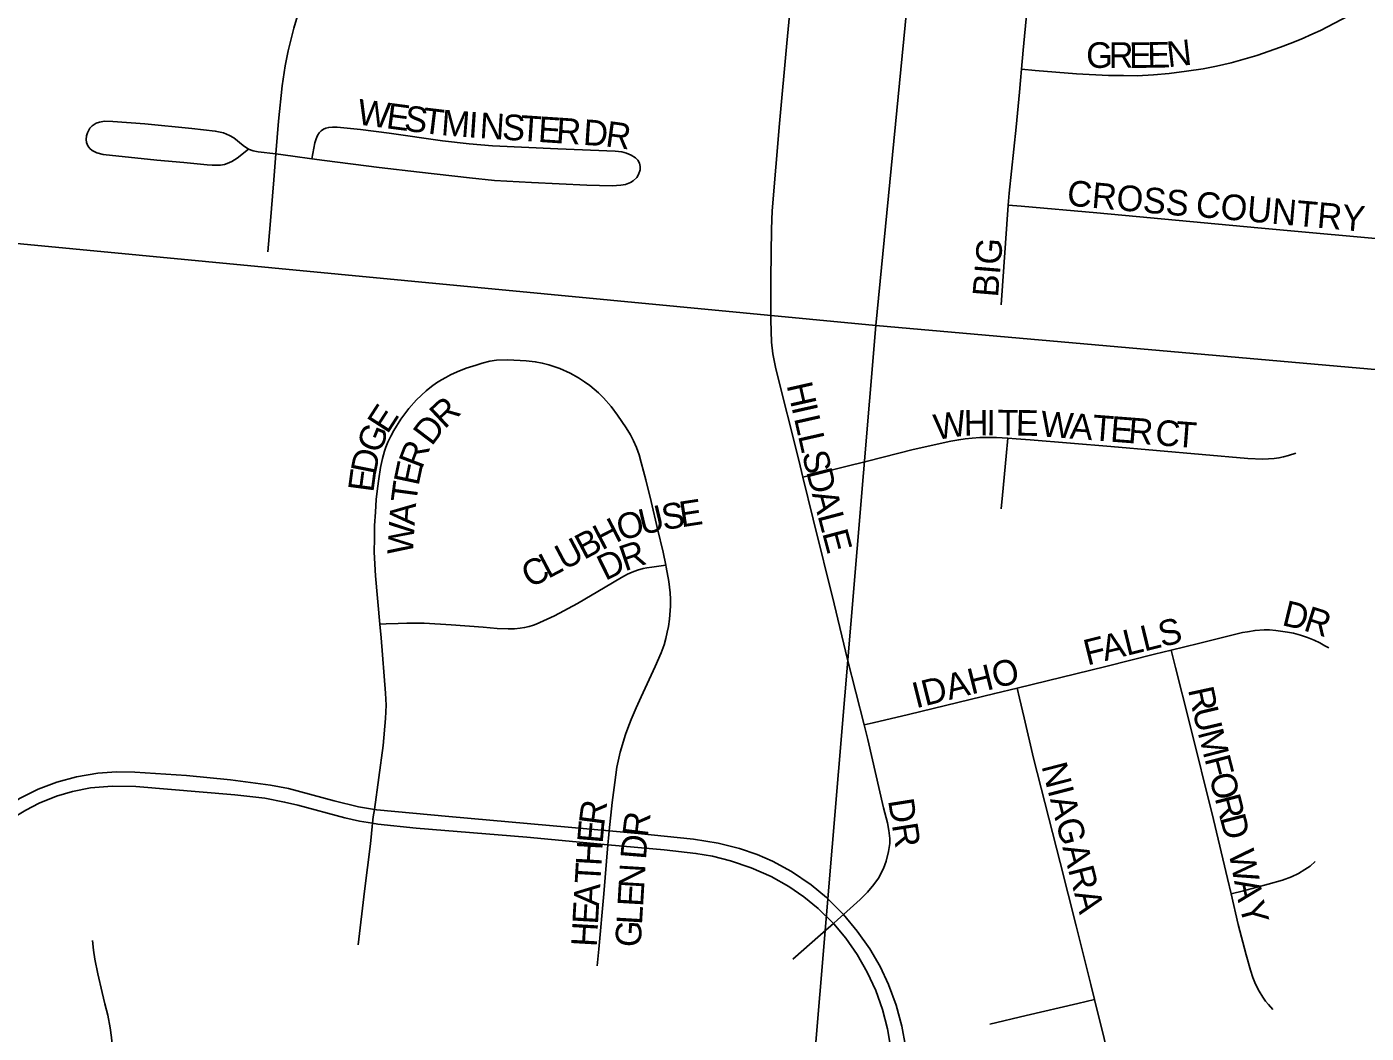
# Model space of a CAD drawing. Extents: x 1410790 to 1770854, y 448063 to 770588.
# Drawn here: x 1532952 to 1535566, y 644079 to 646042 of the extents above; entities that cross this region are included whole.
import ezdxf

# ---------------------------------------------------------------- set-up
doc = ezdxf.new("R2010")
doc.units = 0
for name, color, linetype in [('GM_X_City_Street', 7, 'Continuous'), ('GM_X_City_Street_Text', 7, 'Continuous'), ('GM_X_Section', 7, 'Continuous')]:
    doc.layers.add(name, color=color, linetype=linetype)

msp = doc.modelspace()

# ---------------------------------------------------------------- linework, layer by layer
at = {"layer": 'GM_X_City_Street'}
for points in [[(1534893.3, 645959.4), (1534896.6, 645996.5), (1534903.8, 646071.6), (1534911, 646143.3), (1534916.5, 646202.1), (1534924.4, 646283.3), (1534930.7, 646351.9), (1534938.8, 646435.8)], [(1534466.8, 645163.3), (1534458.7, 645196.4), (1534413.8, 645374.7), (1534408.1, 645404), (1534405.2, 645427.1), (1534404.1, 645470), (1534404.1, 645552.1), (1534405.1, 645647.3), (1534406.6, 645683.5), (1534420.8, 645853.5), (1534435.5, 646010.2), (1534453.9, 646209.5), (1534462.6, 646304)], [(1533438.1, 645794.5), (1533443.1, 645858.3), (1533450.3, 645926.9), (1533456.4, 645966), (1533462, 645995.2), (1533473.2, 646039.9), (1533494.4, 646112.5), (1533502.8, 646139.7)], [(1534893.3, 645959.4), (1534919.8, 645956.9), (1535000.6, 645950.6), (1535063.2, 645947), (1535092.5, 645947.1), (1535118.7, 645946.9), (1535150.7, 645948.5), (1535181.5, 645951), (1535215.2, 645955.6), (1535247.8, 645960.6), (1535273.7, 645965.7), (1535302.1, 645972.2), (1535352.5, 645986.4), (1535398.4, 646002.4), (1535417.7, 646009.9), (1535439.1, 646018.4), (1535461.7, 646028.5), (1535476.5, 646035.2), (1535531.6, 646063.4)], [(1534867.5, 645694.5), (1534869.2, 645717.4), (1534882.5, 645846.6), (1534889.2, 645914.9), (1534891.4, 645937.8), (1534893.3, 645959.4)], [(1533384.7, 645803.8), (1533362.4, 645786), (1533352.1, 645779.5), (1533343.1, 645775.3), (1533337.7, 645773.5), (1533330.3, 645772.4), (1533321.9, 645772.2), (1533314, 645772.3), (1533304.2, 645773), (1533258.5, 645777.6), (1533206.1, 645782), (1533101.4, 645793.1), (1533088.6, 645796.2), (1533079.9, 645800.8), (1533075, 645805.1), (1533071.2, 645810.3), (1533068.8, 645816.3), (1533067.8, 645822.7), (1533068.3, 645829.3), (1533070.2, 645835.7), (1533075.1, 645844.2), (1533079.6, 645848.9), (1533087.7, 645854.3), (1533093.8, 645856.5), (1533103.6, 645858), (1533120.1, 645857.6), (1533182.4, 645853.1), (1533273.9, 645843.9), (1533319.7, 645838.9), (1533335.7, 645835.5), (1533347.7, 645830.5), (1533356.1, 645825.5), (1533374, 645810.9), (1533384.7, 645803.8)], [(1533508.4, 645784.7), (1533532.7, 645781.3), (1533640, 645767.9), (1533718.3, 645758.8), (1533816, 645747.3), (1533865, 645742.7), (1533937, 645738.3), (1534045.1, 645733.3), (1534094.5, 645732), (1534111, 645733.1), (1534120.7, 645734.9), (1534130, 645738.5), (1534135.4, 645741.7), (1534142.6, 645748.5), (1534146.1, 645753.9), (1534149, 645763.1), (1534149.1, 645769.7), (1534147.6, 645776.1), (1534144.6, 645781.8), (1534139.9, 645786.5), (1534131.5, 645791.7), (1534122.6, 645795.8), (1534113.1, 645798.5), (1534100.1, 645799.8), (1533988.7, 645804.1), (1533860.9, 645810.2), (1533815.1, 645813.9), (1533763, 645820.1), (1533658.9, 645834.8), (1533603.5, 645841.6), (1533557.9, 645846.2), (1533548.7, 645846.5), (1533541.4, 645845.9), (1533535.7, 645844.4), (1533531.3, 645842.7), (1533526.8, 645839.5), (1533522.6, 645835.1), (1533519.4, 645830.2), (1533516.7, 645823.5), (1533514.4, 645816.1), (1533508.4, 645784.7)], [(1533384.7, 645803.8), (1533393.9, 645800.1), (1533403.7, 645798.5), (1533438.1, 645794.5)], [(1533422.3, 645603.3), (1533426.7, 645655.8), (1533434.1, 645743.7), (1533438.1, 645794.5)], [(1533438.1, 645794.5), (1533470.9, 645789.9), (1533508.4, 645784.7)], [(1534853.6, 645500.1), (1534867.5, 645694.5)], [(1534867.5, 645694.5), (1534892.4, 645692.3), (1535040.5, 645679.2), (1535354.4, 645650.3), (1535648.3, 645623.2), (1535720.3, 645616.5), (1535763, 645614.2), (1535783.2, 645613.6), (1535803.3, 645615.5), (1535820.8, 645618.8)], [(1533641, 644876.6), (1533632.5, 644971.3), (1533630.1, 645016.9), (1533630.4, 645044.4), (1533630.9, 645068.9), (1533632.4, 645095.4), (1533634.1, 645120.2), (1533636.5, 645141.4), (1533638.8, 645160.1), (1533642.4, 645182.6), (1533646, 645200), (1533650, 645214.1), (1533652.8, 645221.9), (1533656.8, 645231.6), (1533662.2, 645243.5), (1533668.6, 645254.7), (1533682.1, 645276.8), (1533697.3, 645297.8), (1533712.4, 645314.6), (1533731.3, 645332.1), (1533741.6, 645340.5), (1533751.8, 645347.8), (1533761.3, 645353.3), (1533769.6, 645358.1), (1533779, 645363.5), (1533791.9, 645368.9), (1533809.8, 645376.1), (1533828.7, 645382.1)], [(1534199.2, 644991.7), (1534193.8, 645017.4), (1534183.2, 645062.8), (1534170.6, 645115.9), (1534160.2, 645158), (1534151.2, 645192.4), (1534146.9, 645206.8), (1534141.8, 645221.2), (1534136.3, 645234.6), (1534130.4, 645246), (1534121.8, 645259.7), (1534104.8, 645284.8), (1534092.6, 645301.3), (1534077.5, 645318.2), (1534067.7, 645327.9), (1534050.6, 645342.4), (1534040.2, 645349.5), (1534029, 645357.4), (1534012.5, 645366.3), (1533992, 645375.4), (1533970.8, 645382.7), (1533957.9, 645386.1), (1533944.2, 645388.7), (1533926.7, 645390.8), (1533891.1, 645392.4), (1533868.6, 645391.7), (1533855.5, 645389.8), (1533840.7, 645386.1), (1533828.7, 645382.1)], [(1534466.8, 645163.3), (1534500.4, 645171.7), (1534592.5, 645194.6), (1534681.7, 645217.2), (1534755.5, 645233.8), (1534770.8, 645236.5), (1534783.6, 645238.4), (1534797, 645239.9), (1534811.6, 645240.8), (1534828.1, 645240.9), (1534844.6, 645240.8), (1534866.4, 645239.4)], [(1534853.8, 645102), (1534856.2, 645128.5), (1534863.2, 645204.5), (1534866.4, 645239.4)], [(1534866.4, 645239.4), (1534882.9, 645238.4), (1534910.3, 645236.6), (1535067.3, 645223.4), (1535335.1, 645199.9), (1535364.2, 645198.8), (1535375.3, 645199.1), (1535386.6, 645199.7), (1535395.7, 645201.2), (1535404.5, 645203), (1535414.6, 645205.8), (1535428.6, 645210.4)], [(1534586, 644680.1), (1534553.8, 644807.8), (1534527.6, 644916.2), (1534486.8, 645081.8), (1534466.8, 645163.3)], [(1533641, 644876.6), (1533653.2, 644877), (1533676.9, 644877.7), (1533693.4, 644878.4), (1533727.4, 644878.7), (1533780, 644875.5), (1533842.5, 644870.5), (1533869.8, 644868), (1533891.7, 644867.3), (1533903.6, 644867.6), (1533914.8, 644868.7), (1533923.4, 644870.1), (1533932.7, 644872.3), (1533940.7, 644874.9), (1533946.3, 644876.9), (1533982, 644892.8), (1534026.5, 644917.2), (1534080.8, 644948.8), (1534112.8, 644967.4), (1534124.3, 644974), (1534133.3, 644978.3), (1534144, 644982.3), (1534155, 644985.5), (1534162.1, 644986.5), (1534171.8, 644987.9), (1534199.2, 644991.7)], [(1534088.7, 644473.3), (1534094.7, 644529), (1534099.6, 644568), (1534103.8, 644597.5), (1534110, 644626.6), (1534120.5, 644661.5), (1534124.9, 644673.5), (1534131.8, 644690.8), (1534141.5, 644713.4), (1534151, 644734.6), (1534178.4, 644794.2), (1534190.3, 644820.9), (1534195.8, 644836.4), (1534199.4, 644848.6), (1534201.9, 644860.8), (1534204.4, 644872.3), (1534206.3, 644886.1), (1534208.3, 644911.8), (1534208.3, 644925.5), (1534207.7, 644937.5), (1534205, 644959.8), (1534200.1, 644987.7), (1534199.2, 644991.7)], [(1533630.3, 644515.1), (1533638.9, 644577.7), (1533647.2, 644639.7), (1533652.1, 644692.3), (1533653.1, 644718.9), (1533652.1, 644742.1), (1533643.3, 644850.3), (1533641, 644876.6)], [(1535185.1, 644825.9), (1535238.8, 644839), (1535324.7, 644860.1), (1535334.4, 644862), (1535349.1, 644864.5), (1535366.7, 644865.8), (1535377, 644865.5), (1535389.6, 644864.6), (1535412.3, 644861.2), (1535423.9, 644858.8), (1535437.7, 644855.1), (1535451.2, 644850.5), (1535464.5, 644845.2), (1535475.5, 644840.2), (1535485.5, 644834.7), (1535493.1, 644830.2)], [(1534884.8, 644752), (1535057.6, 644794), (1535152.9, 644818), (1535185.1, 644825.9)], [(1535302.3, 644350.3), (1535295.4, 644380.7), (1535267.8, 644495.7), (1535220.6, 644687), (1535193.7, 644792), (1535185.1, 644825.9)], [(1534586, 644680.1), (1534603.5, 644684.2), (1534672.5, 644700.3), (1534841.1, 644741.4), (1534884.8, 644752)], [(1535035.7, 644144.1), (1535028.5, 644173.3), (1534999.9, 644287.8), (1534968.9, 644411.8), (1534916.9, 644614.9), (1534898.2, 644694.2), (1534889.4, 644732.2), (1534884.8, 644752)], [(1534545.7, 644310), (1534578.3, 644339.4), (1534592.6, 644353.5), (1534604.9, 644368.5), (1534614, 644380.8), (1534623.8, 644399.6), (1534629.4, 644414.5), (1534634, 644433), (1534636, 644448.6), (1534636.5, 644458.5), (1534634.4, 644474), (1534631.7, 644489), (1534624.2, 644518.4), (1534593.1, 644651.8), (1534586, 644680.1)], [(1532753, 644406.7), (1532763.3, 644418.3), (1532779.9, 644432.8), (1532797.4, 644445), (1532821.9, 644460.7), (1532899.7, 644512.8), (1532938.8, 644536.9), (1532974.1, 644554.5), (1533010.8, 644568.5), (1533048.8, 644578.7), (1533090.9, 644585.8), (1533126.9, 644588.5), (1533163, 644588), (1533264, 644581.6), (1533349.7, 644572.6), (1533427.6, 644562.7), (1533462.9, 644555.7), (1533551.9, 644532.2), (1533599.6, 644520.2), (1533630.3, 644515.1)], [(1532753, 644406.7), (1532771.6, 644407.6), (1532786.3, 644410.4), (1532797.1, 644413.7), (1532811.5, 644419.6), (1532850.3, 644444.6), (1532922.2, 644496.5), (1532950.1, 644513.8), (1532976.3, 644527.4), (1533009.7, 644541), (1533041, 644550.4), (1533076.4, 644557.3), (1533118.9, 644560.8), (1533164.8, 644559.8), (1533357.8, 644543.6), (1533416.5, 644536.9), (1533455.1, 644529.6), (1533480.7, 644523.5), (1533572.5, 644498.7), (1533601.4, 644492.5), (1533627, 644488.3)], [(1533628.3, 644500.4), (1533630.3, 644515.1)], [(1533630.3, 644515.1), (1533635.1, 644514.3), (1533775.7, 644501.4), (1534088.7, 644473.3)], [(1533598.7, 644250.8), (1533610.8, 644355.7), (1533622.5, 644448.1), (1533627, 644488.3)], [(1533627, 644488.3), (1533628.3, 644500.4)], [(1533627, 644488.3), (1533637, 644486.7), (1533712, 644478.6), (1533927.9, 644461.3), (1534086.1, 644446.4)], [(1534086.1, 644446.4), (1534087.2, 644458.8)], [(1534087.2, 644458.8), (1534088.7, 644473.3)], [(1534088.7, 644473.3), (1534145.2, 644468.2), (1534252.9, 644456.9), (1534301.5, 644449.2), (1534343, 644439.2), (1534377.1, 644427.5), (1534407.2, 644414.4), (1534444.6, 644394), (1534482.7, 644368.2), (1534513, 644343.1), (1534543.2, 644313), (1534545.7, 644310)], [(1534065.1, 644209.8), (1534068.3, 644242.6), (1534078, 644350.7), (1534086.1, 644446.4)], [(1534086.1, 644446.4), (1534195.8, 644436.1), (1534257.8, 644429.3), (1534290.1, 644423.7), (1534325.1, 644415.1), (1534365.5, 644401.4), (1534404.5, 644384.1), (1534438.9, 644365), (1534468.7, 644344.7), (1534496.6, 644321.8), (1534526.1, 644292.5)], [(1535302.3, 644350.3), (1535326.5, 644356.6), (1535374.6, 644369.1), (1535402.8, 644377.4), (1535420.4, 644383.9), (1535433.8, 644389.9), (1535446.2, 644397.8), (1535456.4, 644404.2), (1535466.6, 644413.5)], [(1535383.4, 644125), (1535375.1, 644134.4), (1535369.5, 644141.1), (1535364.2, 644148.7), (1535357, 644160.6), (1535350.1, 644174), (1535345, 644186.9), (1535340.4, 644201.2), (1535331.6, 644231.3), (1535315.9, 644290.9), (1535302.3, 644350.3)], [(1534535, 644300.4), (1534545.7, 644310)], [(1534545.7, 644310), (1534572.7, 644277.7), (1534597.3, 644242.9), (1534617.1, 644208.9), (1534634, 644173.3), (1534648.7, 644133.3), (1534659.8, 644092.1), (1534666.7, 644053.3), (1534670, 644014.1), (1534669.5, 643971.4), (1534658.6, 643842.5), (1534650.1, 643749)], [(1534446.8, 644222.8), (1534501.1, 644270.5), (1534526.1, 644292.5)], [(1534526.1, 644292.5), (1534535, 644300.4)], [(1534526.1, 644292.5), (1534526.9, 644291.8), (1534550.1, 644264.2), (1534572.6, 644231.9), (1534592.2, 644197.8), (1534608.7, 644162), (1534622, 644125), (1534632, 644086.9), (1534639, 644044.8), (1534642.1, 644005.6), (1534641.1, 643959.6), (1534622.7, 643751.6)], [(1533087.6, 643601.4), (1533091.2, 643641.3), (1533100.3, 643745.9), (1533106.3, 643811.2), (1533112.6, 643893.6), (1533116.3, 643933.9), (1533118.5, 643968.4), (1533119.9, 643986), (1533120.8, 643999.6), (1533120.3, 644021.8), (1533119.4, 644049.9), (1533117.6, 644069.9), (1533114.7, 644088.9), (1533110.4, 644113.9), (1533104.5, 644135.6), (1533099, 644157.7), (1533090.4, 644194.3), (1533084.5, 644223.3), (1533082.3, 644240.6), (1533080, 644259.2)], [(1534831.5, 644096.2), (1534902.1, 644113), (1535003.2, 644136.5), (1535035.7, 644144.1)], [(1534980.8, 643755.3), (1534981.3, 643755.6), (1534996.6, 643766.2), (1535006.3, 643773.7), (1535018.2, 643784), (1535028.3, 643793.7), (1535035.5, 643801.8), (1535041.5, 643809.7), (1535047.6, 643817.7), (1535057.9, 643835.1), (1535066.2, 643853.4), (1535072.7, 643872.5), (1535077.8, 643895.5), (1535080.2, 643915.5), (1535080.8, 643926.1), (1535080.5, 643935.7), (1535078.7, 643955.7), (1535072.9, 643985.1), (1535054.5, 644068.3), (1535035.7, 644144.1)]]:
    msp.add_lwpolyline(points, dxfattribs=at)
at = {"layer": 'GM_X_Section'}
for points in [[(1535136.5, 650861.1), (1534609.1, 645459.7), (1529389.2, 645957.9), (1529818.7, 651249.1)], [(1540640, 650339.9), (1540107.2, 644974.6), (1534609.1, 645459.7), (1535136.5, 650861.1)], [(1534609.1, 645459.7), (1534160.3, 640098.2), (1528881.3, 640647.9), (1529389.2, 645957.9)], [(1534609.1, 645459.7), (1540107.2, 644974.6), (1539587.8, 639581.9), (1534160.3, 640098.2)]]:
    msp.add_lwpolyline(points, close=True, dxfattribs=at)

# ---------------------------------------------------------------- texts
at = {"layer": 'GM_X_City_Street_Text'}
for s, rotation, p in [('G', 0.0656, (1535019.5, 645962.1)), ('R', 0.0653, (1535063.5, 645962.2)), ('E', 0.0546, (1535103.1, 645962.2)), ('E', 0.9681, (1535139.1, 645962.3)), ('N', 6.4207, (1535179.5, 645963.2)), ('W', 352.5309, (1533595.1, 645852.1)), ('E', 352.5209, (1533651.8, 645844.6)), ('S', 352.5209, (1533686.7, 645840)), ('T', 353.0071, (1533722.1, 645835.4)), ('M', 355.6007, (1533759.5, 645830.9)), ('I', 356.2222, (1533812.7, 645826.8)), ('N', 356.2432, (1533834.7, 645825.3)), ('S', 356.2268, (1533878.6, 645822.4)), ('T', 356.2268, (1533913.7, 645820.1)), ('E', 356.2268, (1533948.8, 645817.8)), ('R', 356.2356, (1533984, 645815.5)), ('D', 356.2323, (1534036.7, 645812)), ('R', 352.2786, (1534079.7, 645809.2)), ('CROSS', 354.8033, (1534980.7, 645693.7)), ('COUNTRY', 354.8803, (1535231.9, 645671.7)), ('BIG', 85.2386, (1534847.3, 645513.5)), ('H', 282.6948, (1534434.6, 645343.2)), ('E', 57.1433, (1533655.8, 645246.1)), ('R', 43.1707, (1533767.3, 645256.1)), ('I', 282.6792, (1534444.3, 645300.3)), ('W', 8.8791, (1534726.2, 645235.8)), ('H', 0.6338, (1534780.8, 645244.4)), ('I', 359.9126, (1534824.6, 645244.9)), ('T', 359.939, (1534846.7, 645244.9)), ('E', 358.6338, (1534881.6, 645244.9)), ('D', 52.8372, (1533742.2, 645222.7)), ('L', 282.6995, (1534449.1, 645278.8)), ('W', 355.6922, (1534929.3, 645243.3)), ('A', 355.6021, (1534986.3, 645239)), ('T', 355.5971, (1535030.1, 645235.7)), ('E', 355.6001, (1535065.3, 645233)), ('R', 355.6004, (1535100.3, 645230.3)), ('C', 355.6165, (1535153, 645226.2)), ('T', 355.5971, (1535192.5, 645223.2)), ('G', 68.3082, (1533640.7, 645207.5)), ('L', 282.6977, (1534456.9, 645244.5)), ('D', 78.7586, (1533632.8, 645166.7)), ('R', 68.9607, (1533723.1, 645177.6)), ('E', 78.0846, (1533716.4, 645145.2)), ('S', 282.9013, (1534464.7, 645209.9)), ('E', 82.4243, (1533628.3, 645132.6)), ('D', 284.261, (1534472.8, 645174.4)), ('T', 82.3837, (1533711.9, 645111.2)), ('A', 85.8443, (1533708.8, 645068.2)), ('S', 8.7503, (1534194.6, 645060.1)), ('E', 8.7503, (1534229.4, 645065.5)), ('A', 284.8099, (1534483.8, 645131.2)), ('O', 14.5823, (1534110.5, 645039.3)), ('U', 13.2092, (1534152.8, 645050.3)), ('L', 284.8242, (1534495, 645088.6)), ('W', 86.7362, (1533705.5, 645011.3)), ('B', 27.8693, (1534039.3, 645001.6)), ('H', 27.3666, (1534074.2, 645020.1)), ('E', 284.8415, (1534504, 645054.6)), ('U', 27.8598, (1534000.4, 644981.1)), ('R', 18.8459, (1534119.1, 644979.4)), ('L', 27.8603, (1533969.3, 644964.6)), ('D', 26.2865, (1534081.2, 644960.6)), ('C', 27.8739, (1533934.2, 644946.1)), ('D', 346.2977, (1535399.6, 644875.2)), ('R', 342.5098, (1535441.5, 644865)), ('S', 13.7944, (1535166.9, 644831.6)), ('F', 13.8209, (1535021.6, 644795.9)), ('A', 13.7924, (1535055.8, 644804.3)), ('L', 13.8076, (1535098.6, 644814.8)), ('L', 13.8209, (1535132.7, 644823.2)), ('IDAHO', 14.0339, (1534687.2, 644712.3)), ('R', 282.1626, (1535217.9, 644749.1)), ('U', 283.2776, (1535226.5, 644709.4)), ('M', 284.5022, (1535236.9, 644665.4)), ('F', 284.5443, (1535250.1, 644614.2)), ('NIAGARA', 284.4709, (1534931.8, 644599.9)), ('O', 284.5345, (1535258.9, 644580.2)), ('R', 284.5349, (1535270, 644537.6)), ('R', 82.4503, (1534078.7, 644482.3)), ('DR', 278.9732, (1534632.7, 644532.9)), ('E', 85.1728, (1534075.8, 644447.8)), ('R', 82.878, (1534163.7, 644459.7)), ('D', 284.5317, (1535279.9, 644499.2)), ('D', 85.3071, (1534160.2, 644416.4)), ('H', 86.6759, (1534073.3, 644404.2)), ('W', 280.9357, (1535297.1, 644432)), ('T', 86.6782, (1534071.2, 644369.1)), ('N', 86.5123, (1534156.7, 644359.6)), ('A', 86.665, (1534068.7, 644325.1)), ('E', 86.6393, (1534154.6, 644324.5)), ('A', 280.9419, (1535308, 644375.8)), ('E', 86.6835, (1534066.6, 644290)), ('Y', 285.2013, (1535317.3, 644328.7)), ('L', 86.6247, (1534152.5, 644289.4)), ('H', 86.665, (1534064.1, 644246.1)), ('G', 86.6322, (1534149.9, 644245.4))]:
    msp.add_text(s, height=50, rotation=rotation, dxfattribs=at).set_placement(p)

doc.saveas('drawing.dxf')
